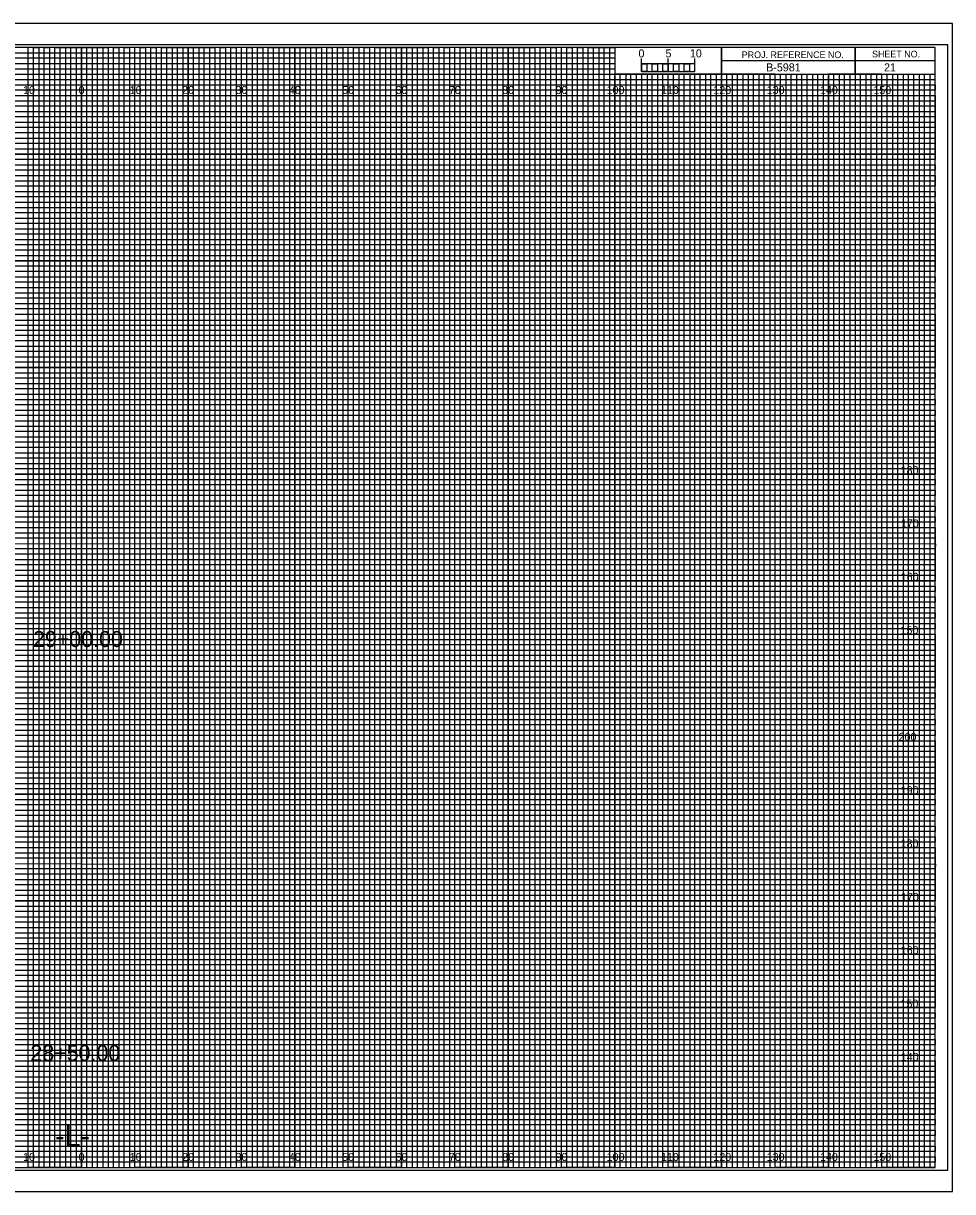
# Model space of a CAD drawing. Extents: x -13 to 323, y -5 to 4174.
# Drawn here: x 149.1 to 323.3, y 3295.5 to 3514.5 of the extents above; entities that cross this region are included whole.
import ezdxf

# ---------------------------------------------------------------- set-up
doc = ezdxf.new("R2010")
doc.units = 0
for name, color, linetype in [('Exist Cross Section Cell', 7, 'Continuous'), ('Exist XS Center Line Elevation Label', 7, 'Continuous'), ('Exist XS Ground Line', 7, 'Continuous'), ('Prop CMT Concrete Structures', 7, 'Continuous'), ('Prop CMT Guardrail Graphics', 7, 'Continuous'), ('Prop CMT Pvmt Course 1', 7, 'Continuous'), ('Prop CMT Pvmt Course 2', 7, 'Continuous'), ('Prop CMT Pvmt Course 3', 7, 'Continuous'), ('Prop CMT Pvmt Surface', 7, 'Continuous'), ('Prop CMT Shld Paved Course 1', 7, 'Continuous'), ('Prop CMT Shld Paved Course 2', 7, 'Continuous'), ('Prop CMT Shld Paved Course 3', 7, 'Continuous'), ('Prop CMT Subgrade Earthwork', 7, 'Continuous'), ('Prop XS Ditch Standard Text', 7, 'Continuous'), ('Prop XS SE Text', 7, 'Continuous'), ('Prop XS Side Slope Text', 7, 'Continuous'), ('Scratch_Level_0', 7, 'Continuous')]:
    doc.layers.add(name, color=color, linetype=linetype)

msp = doc.modelspace()

# ---------------------------------------------------------------- linework, layer by layer
at = {"layer": 'Exist XS Center Line Elevation Label'}
for points in [[(145, 3300), (155, 3300), (155, 3510), (165, 3510), (165, 3300), (175, 3300), (175, 3510), (185, 3510), (185, 3300), (195, 3300), (195, 3510), (205, 3510), (205, 3300), (215, 3300), (215, 3510), (225, 3510), (225, 3300), (235, 3300), (235, 3510), (245, 3510), (245, 3300), (255, 3300), (255, 3510), (259.93, 3510), (260, 3510), (260, 3505), (264.99, 3505), (264.99, 3300), (275, 3300), (275, 3505), (285, 3505), (285, 3300), (295, 3300), (295, 3505), (305, 3505), (305, 3300), (315, 3300), (315, 3505)], [(0, 3505), (275, 3505)], [(0, 3485), (320, 3485), (320, 3495), (0, 3495)], [(0, 3465), (320, 3465), (320, 3475), (0, 3475)], [(0, 3445), (320, 3445), (320, 3455), (0, 3455)], [(0, 3425), (320, 3425), (320, 3435), (0, 3435)], [(0, 3405), (320, 3405), (320, 3415), (0, 3415)], [(0, 3385), (320, 3385), (320, 3395), (0, 3395)], [(0, 3365), (320, 3365), (320, 3375), (0, 3375)], [(0, 3345), (320, 3345), (320, 3355), (0, 3355)], [(0, 3325), (320, 3325), (320, 3335), (0, 3335)], [(0, 3305), (320, 3305), (320, 3315), (0, 3315)]]:
    msp.add_lwpolyline(points, dxfattribs=at)
at = {"layer": 'Exist XS Ground Line'}
for p, q in [((150, 3510), (140, 3510)), ((150, 3300), (150, 3510)), ((170, 3510), (160, 3510)), ((160, 3510), (160, 3300)), ((170, 3300), (170, 3510)), ((190, 3510), (180, 3510)), ((180, 3510), (180, 3300)), ((190, 3300), (190, 3510)), ((210, 3510), (200, 3510)), ((200, 3510), (200, 3300)), ((210, 3300), (210, 3510)), ((230, 3510), (220, 3510)), ((220, 3510), (220, 3300)), ((230, 3300), (230, 3510)), ((250, 3510), (240, 3510)), ((240, 3510), (240, 3300)), ((250, 3300), (250, 3510)), ((260, 3510), (260, 3300)), ((270, 3300), (270, 3505)), ((290, 3505), (280, 3505)), ((280, 3505), (280, 3300)), ((290, 3300), (290, 3505)), ((310, 3505), (300, 3505)), ((300, 3505), (300, 3300)), ((310, 3300), (310, 3505)), ((160, 3300), (150, 3300)), ((180, 3300), (170, 3300)), ((200, 3300), (190, 3300)), ((220, 3300), (210, 3300)), ((240, 3300), (230, 3300)), ((260, 3300), (250, 3300)), ((280, 3300), (270, 3300)), ((300, 3300), (290, 3300)), ((320, 3300), (310, 3300)), ((320, 3300), (320, 3300))]:
    msp.add_line(p, q, dxfattribs=at)
for points in [[(0, 3500), (320, 3500), (320, 3490), (0, 3490)], [(0, 3480), (320, 3480), (320, 3470), (0, 3470)], [(0, 3460), (320, 3460), (320, 3450), (0, 3450)], [(0, 3440), (320, 3440), (320, 3430), (0, 3430)], [(0, 3420), (320, 3420), (320, 3410), (0, 3410)], [(0, 3400), (320, 3400), (320, 3390), (0, 3390)], [(0, 3380), (320, 3380), (320, 3370), (0, 3370)], [(0, 3360), (320, 3360), (320, 3350), (0, 3350)], [(0, 3340), (320, 3340), (320, 3330), (0, 3330)], [(0, 3320), (320, 3320), (320, 3310), (0, 3310)]]:
    msp.add_lwpolyline(points, dxfattribs=at)
at = {"layer": 'Prop CMT Pvmt Course 1'}
for p, q in [((323.3, 3514.5), (-13.4, 3514.5)), ((-13.4, 3295.5), (323.3, 3295.5))]:
    msp.add_line(p, q, dxfattribs=at)
at = {"layer": 'Prop CMT Pvmt Course 2'}
msp.add_lwpolyline([(-13.4, 3295.5), (323.3, 3295.5), (323.3, 3514.5), (-13.4, 3514.5)], close=True, dxfattribs=at)
at = {"layer": 'Prop CMT Pvmt Course 3'}
msp.add_lwpolyline([(-10.8, 3299.5), (322.4, 3299.5), (322.4, 3510.5), (-10.8, 3510.5)], close=True, dxfattribs=at)
at = {"layer": 'Prop CMT Shld Paved Course 1'}
for p, q in [((305, 3510), (305, 3505)), ((305, 3505), (305, 3510)), ((280, 3507.5), (280, 3505)), ((320, 3507.49), (280, 3507.49)), ((280, 3505), (320, 3505))]:
    msp.add_line(p, q, dxfattribs=at)
for points in [[(320, 3510), (0, 3510), (0, 3300), (320, 3300)], [(280, 3510), (260, 3510), (260, 3505.03), (280, 3505.03)], [(320, 3510), (280, 3510), (280, 3505), (320, 3505)]]:
    msp.add_lwpolyline(points, close=True, dxfattribs=at)
at = {"layer": 'Prop CMT Shld Paved Course 2'}
for p, q in [((267, 3505), (266.01, 3505)), ((266.01, 3505), (266.01, 3300)), ((267, 3300), (267, 3505)), ((269, 3505), (268, 3505)), ((268, 3505), (268, 3300)), ((269, 3300), (269, 3505)), ((266.01, 3300), (265, 3300)), ((268, 3300), (267, 3300))]:
    msp.add_line(p, q, dxfattribs=at)
for points in [[(150, 3300), (151, 3300), (151, 3510), (152, 3510), (152, 3300)], [(152, 3300), (153, 3300), (153, 3510), (154, 3510), (154, 3300)], [(155, 3300), (156, 3300), (156, 3510), (157, 3510), (157, 3300)], [(157, 3300), (158, 3300), (158, 3510), (159, 3510), (159, 3300)], [(160, 3300), (161, 3300), (161, 3510), (162, 3510), (162, 3300)], [(162, 3300), (163, 3300), (163, 3510), (164, 3510), (164, 3300)], [(165, 3300), (166, 3300), (166, 3510), (167, 3510), (167, 3300)], [(167, 3300), (168, 3300), (168, 3510), (169, 3510), (169, 3300)], [(170, 3300), (171, 3300), (171, 3510), (172, 3510), (172, 3300)], [(172, 3300), (173, 3300), (173, 3510), (174, 3510), (174, 3300)], [(175, 3300), (176, 3300), (176, 3510), (177, 3510), (177, 3300)], [(177, 3300), (178, 3300), (178, 3510), (179, 3510), (179, 3300)], [(180, 3300), (181, 3300), (181, 3510), (182, 3510), (182, 3300)], [(182, 3300), (183, 3300), (183, 3510), (184, 3510), (184, 3300)], [(185, 3300), (186, 3300), (186, 3510), (187, 3510), (187, 3300)], [(187, 3300), (188, 3300), (188, 3510), (189, 3510), (189, 3300)], [(190, 3300), (191, 3300), (191, 3510), (192, 3510), (192, 3300)], [(192, 3300), (193, 3300), (193, 3510), (194, 3510), (194, 3300)], [(195, 3300), (196, 3300), (196, 3510), (197, 3510), (197, 3300)], [(197, 3300), (198, 3300), (198, 3510), (199, 3510), (199, 3300)], [(200, 3300), (201, 3300), (201, 3510), (202, 3510), (202, 3300)], [(202, 3300), (203, 3300), (203, 3510), (204, 3510), (204, 3300)], [(205, 3300), (206, 3300), (206, 3510), (207, 3510), (207, 3300)], [(207, 3300), (208, 3300), (208, 3510), (209, 3510), (209, 3300)], [(210, 3300), (211, 3300), (211, 3510), (212, 3510), (212, 3300)], [(212, 3300), (213, 3300), (213, 3510), (214, 3510), (214, 3300)], [(215, 3300), (216, 3300), (216, 3510), (217, 3510), (217, 3300)], [(217, 3300), (218, 3300), (218, 3510), (219, 3510), (219, 3300)], [(220, 3300), (221, 3300), (221, 3510), (222, 3510), (222, 3300)], [(222, 3300), (223, 3300), (223, 3510), (224, 3510), (224, 3300)], [(225, 3300), (226, 3300), (226, 3510), (227, 3510), (227, 3300)], [(227, 3300), (228, 3300), (228, 3510), (229, 3510), (229, 3300)], [(230, 3300), (231, 3300), (231, 3510), (232, 3510), (232, 3300)], [(232, 3300), (233, 3300), (233, 3510), (234, 3510), (234, 3300)], [(235, 3300), (236, 3300), (236, 3510), (237, 3510), (237, 3300)], [(237, 3300), (238, 3300), (238, 3510), (239, 3510), (239, 3300)], [(240, 3300), (241, 3300), (241, 3510), (242, 3510), (242, 3300)], [(242, 3300), (243, 3300), (243, 3510), (244, 3510), (244, 3300)], [(245, 3300), (246, 3300), (246, 3510), (247, 3510), (247, 3300)], [(247, 3300), (248, 3300), (248, 3510), (249, 3510), (249, 3300)], [(250, 3300), (251, 3300), (251, 3510), (252, 3510), (252, 3300)], [(252, 3300), (253, 3300), (253, 3510), (254, 3510), (254, 3300)], [(255, 3300), (256, 3300), (256, 3510), (257, 3510), (257, 3300)], [(257, 3300), (258, 3300), (258, 3510), (259, 3510), (259, 3300)], [(260, 3300), (261, 3300), (261, 3505), (262.02, 3505), (262.02, 3300)], [(262, 3300), (263, 3300), (263, 3505), (263.99, 3505), (263.99, 3300)], [(270, 3300), (270.98, 3300), (270.98, 3505), (272, 3505), (272, 3300)], [(272, 3300), (273, 3300), (273, 3505), (274.05, 3505), (274.05, 3300)], [(275, 3300), (276, 3300), (276, 3505), (277, 3505), (277, 3300)], [(277, 3300), (278, 3300), (278, 3505), (279, 3505), (279, 3300)], [(280, 3300), (281, 3300), (281, 3505), (282, 3505), (282, 3300)], [(282, 3300), (283, 3300), (283, 3505), (284, 3505), (284, 3300)], [(285, 3300), (286, 3300), (286, 3505), (287, 3505), (287, 3300)], [(287, 3300), (288, 3300), (288, 3505), (289, 3505), (289, 3300)], [(290, 3300), (291, 3300), (291, 3505), (292, 3505), (292, 3300)], [(292, 3300), (293, 3300), (293, 3505), (294, 3505), (294, 3300)], [(295, 3300), (296, 3300), (296, 3505), (297, 3505), (297, 3300)], [(297, 3300), (298, 3300), (298, 3505), (299, 3505), (299, 3300)], [(300, 3300), (301, 3300), (301, 3505), (302, 3505), (302, 3300)], [(302, 3300), (303, 3300), (303, 3505), (304, 3505), (304, 3300)], [(305, 3300), (306, 3300), (306, 3505), (307, 3505), (307, 3300)], [(307, 3300), (308, 3300), (308, 3505), (309, 3505), (309, 3300)], [(310, 3300), (311, 3300), (311, 3505), (312, 3505), (312, 3300)], [(312, 3300), (313, 3300), (313, 3505), (314, 3505), (314, 3300)], [(315, 3300), (316, 3300), (316, 3505), (317, 3505), (317, 3300)], [(317, 3300), (318, 3300), (318, 3505), (319, 3505), (319, 3300)]]:
    msp.add_lwpolyline(points, dxfattribs=at)
at = {"layer": 'Prop CMT Shld Paved Course 3'}
for p, q in [((265, 3505.49), (265, 3507.9)), ((265, 3506.9), (265, 3507.9)), ((270, 3505.49), (270, 3507.9)), ((275, 3505.49), (275, 3507.9)), ((275, 3506.9), (275, 3507.9))]:
    msp.add_line(p, q, dxfattribs=at)
for points in [[(275, 3506.9), (265, 3506.9), (265, 3505.49), (275, 3505.49)], [(265, 3506.9), (266, 3506.9), (266, 3505.49), (265, 3505.49)], [(267, 3506.9), (268, 3506.9), (268, 3505.49), (267, 3505.49)], [(269, 3506.9), (270, 3506.9), (270, 3505.49), (269, 3505.49)], [(271, 3506.9), (272, 3506.9), (272, 3505.49), (271, 3505.49)], [(273, 3506.9), (274, 3506.9), (274, 3505.49), (273, 3505.49)]]:
    msp.add_lwpolyline(points, close=True, dxfattribs=at)
at = {"layer": 'Prop CMT Subgrade Earthwork'}
for p, q in [((150, 3300), (150, 3510)), ((160, 3300), (160, 3510)), ((170, 3300), (170, 3510)), ((180, 3300), (180, 3510)), ((190, 3300), (190, 3510)), ((200, 3300), (200, 3510)), ((210, 3300), (210, 3510)), ((220, 3300), (220, 3510)), ((230, 3300), (230, 3510)), ((240, 3300), (240, 3510)), ((250, 3300), (250, 3510)), ((260, 3300), (260, 3504.69)), ((270, 3300), (270, 3504.69)), ((280, 3300), (280, 3504.69)), ((290, 3300), (290, 3504.69)), ((300, 3300), (300, 3504.69)), ((310, 3300), (310, 3504.69)), ((0, 3500), (320, 3500)), ((0, 3490), (320, 3490)), ((0, 3480), (320, 3480)), ((0, 3470), (320, 3470)), ((0, 3460), (320, 3460)), ((0, 3450), (320, 3450)), ((0, 3440), (320, 3440)), ((0, 3430), (320, 3430)), ((0, 3420), (320, 3420)), ((0, 3410), (320, 3410)), ((0, 3400), (320, 3400)), ((0, 3390), (320, 3390)), ((0, 3380), (320, 3380)), ((0, 3370), (320, 3370)), ((0, 3360), (320, 3360)), ((0, 3350), (320, 3350)), ((0, 3340), (320, 3340)), ((0, 3330), (320, 3330)), ((0, 3320), (320, 3320)), ((0, 3310), (320, 3310))]:
    msp.add_line(p, q, dxfattribs=at)
at = {"layer": 'Scratch_Level_0'}
for p, q in [((0, 3509), (260, 3509)), ((260, 3509), (260, 3507.98)), ((260, 3507.98), (0, 3507.98)), ((0, 3507), (260, 3507)), ((260, 3507), (260, 3505.89)), ((260, 3505.89), (0, 3505.89)), ((0, 3504), (320, 3504))]:
    msp.add_line(p, q, dxfattribs=at)
for points in [[(0, 3503), (270, 3503), (320, 3503), (320, 3502), (0, 3502)], [(0, 3501), (320, 3501), (320, 3499), (0, 3499)], [(0, 3498), (320, 3498), (320, 3497), (0, 3496.98)], [(0, 3496), (320, 3496), (320, 3494), (0, 3494)], [(0, 3493), (320, 3493), (320, 3492), (0, 3492)], [(0, 3491), (320, 3491), (320, 3489), (0, 3489)], [(0, 3488), (320, 3488), (320, 3487), (0, 3487)], [(0, 3486), (320, 3486), (320, 3484), (0, 3484)], [(0, 3483), (320, 3483), (320, 3482), (0, 3482)], [(0, 3481), (320, 3481), (320, 3479), (0, 3479)], [(0, 3478), (320, 3478), (320, 3477), (0, 3477)], [(0, 3476), (320, 3476), (320, 3473.95), (320, 3473), (320, 3472), (0, 3472)], [(0, 3474), (320, 3474), (320, 3473), (0, 3473)], [(0, 3471), (320, 3471), (320, 3469), (0, 3469.03)], [(0, 3469.03), (320, 3469), (320, 3468), (0, 3468)], [(0, 3467), (320, 3467), (320, 3466), (0, 3466)], [(0, 3464), (320, 3464), (320, 3463), (0, 3463)], [(0, 3462), (320, 3462), (320, 3461), (0, 3461)], [(-0.07, 3458.89), (320, 3458.89), (320, 3457.88), (-0.07, 3457.88)], [(0, 3457), (320, 3457), (320, 3456), (0, 3456)], [(0, 3454), (320, 3454), (320, 3453), (0, 3453)], [(0, 3452), (320, 3452), (320, 3451), (0, 3451)], [(0, 3449), (320, 3449), (320, 3448), (0, 3448)], [(0, 3447), (320, 3447), (320, 3446), (0, 3446)], [(0, 3444), (320, 3444), (320, 3443), (0, 3443)], [(0, 3442), (320, 3442), (320, 3441), (0, 3441)], [(0, 3439), (320, 3439), (319.99, 3437.98), (0, 3438)], [(0, 3437), (320, 3437), (320, 3436), (0, 3436)], [(0, 3434), (320, 3434), (320, 3433), (0, 3433)], [(0, 3432), (320, 3432), (320, 3431), (0, 3431)], [(0, 3429), (320, 3429), (320, 3428), (0, 3428)], [(0, 3427), (320, 3427), (320, 3426), (0, 3426)], [(0, 3424), (320, 3424), (320, 3423), (0, 3423)], [(0, 3422), (320, 3422), (320, 3421), (0, 3421)], [(0, 3419), (320, 3419), (320, 3418), (0, 3418)], [(0, 3416.99), (320.07, 3416.91), (320, 3416), (0, 3416)], [(0, 3414), (320, 3414), (320, 3413), (0, 3413)], [(0, 3412), (320, 3412), (320, 3411), (0, 3411)], [(0, 3409), (320, 3409), (320, 3408), (0, 3408)], [(0, 3407), (320, 3407), (320, 3406), (0, 3406)], [(0, 3404), (320, 3404), (320, 3403), (0, 3403)], [(0, 3402), (320, 3402), (320, 3401), (0, 3401)], [(0, 3399), (320, 3399), (320, 3398), (0, 3398)], [(0, 3397), (320, 3397), (320, 3396), (0, 3396)], [(0, 3394), (320, 3394), (320, 3393), (0, 3393)], [(0, 3392), (320, 3392), (320, 3391), (0, 3391)], [(0, 3389), (320, 3389), (320, 3388), (0, 3388)], [(0, 3387), (320, 3387), (320, 3386), (0, 3386)], [(0, 3384), (320, 3384), (320, 3383), (0, 3383)], [(0, 3382), (320, 3382), (320, 3381), (0, 3381)], [(0, 3379), (320, 3379), (319.99, 3377.98), (0, 3378)], [(0, 3377), (320, 3377), (320, 3376), (0, 3376)], [(0, 3374), (320, 3374), (320, 3373), (0, 3373)], [(0, 3372), (320, 3372), (320, 3371), (0, 3371)], [(0, 3369), (320, 3369), (320, 3368), (0, 3368)], [(0, 3367), (320, 3367), (320, 3366), (0, 3366)], [(0, 3364), (320, 3364), (320, 3363), (0, 3363)], [(0, 3362), (320, 3362), (320, 3361), (0, 3361)], [(0, 3359), (320, 3359), (320, 3358), (0, 3358)], [(0, 3356.99), (320.07, 3356.91), (320, 3356), (0, 3356)], [(0, 3354), (320, 3354), (320, 3353), (0, 3353)], [(0, 3352), (320, 3352), (320, 3351), (0, 3351)], [(0, 3349), (320, 3349), (320, 3348), (0, 3348)], [(0, 3347), (320, 3347), (320, 3346), (0, 3346)], [(0, 3344), (320, 3344), (320, 3343), (0, 3343)], [(0, 3342), (320, 3342), (320, 3341), (0, 3341)], [(0, 3339), (320, 3339), (320, 3338), (0, 3338)], [(0, 3337), (320, 3337), (320, 3336), (0, 3336)], [(0, 3334), (320, 3334), (320, 3333), (0, 3333)], [(0, 3332), (320, 3332), (320, 3331), (0, 3331)], [(0, 3329), (320, 3329), (320, 3328), (0, 3328)], [(0, 3327), (320, 3327), (320, 3326), (0, 3326)], [(0, 3324), (320, 3324), (320, 3323), (0, 3323)], [(0, 3322), (320, 3322), (320, 3321), (0, 3321)], [(0, 3319), (320, 3319), (320, 3318), (0, 3318)], [(0, 3317), (320, 3317), (320, 3316), (0, 3316)], [(0, 3314), (320, 3314), (320, 3313), (0, 3313)], [(0, 3312), (320, 3312), (320, 3311), (0, 3311)], [(0, 3309), (320, 3309), (320, 3308), (0, 3308)], [(0, 3307), (320, 3307), (320, 3306), (0, 3306)], [(0, 3304), (320, 3304), (320, 3303), (0, 3303)], [(0, 3302), (320, 3302), (320, 3301), (0, 3301)]]:
    msp.add_lwpolyline(points, dxfattribs=at)

# ---------------------------------------------------------------- texts
at = {"layer": 'Exist Cross Section Cell'}
for s, p in [('10', (149.04, 3501.25)), ('0', (159.45, 3501.25)), ('0', (159.45, 3501.25)), ('10', (169.04, 3501.25)), ('20', (178.86, 3501.25)), ('30', (188.86, 3501.25)), ('40', (198.86, 3501.25)), ('50', (208.86, 3501.25)), ('60', (218.86, 3501.25)), ('70', (228.86, 3501.25)), ('80', (238.86, 3501.25)), ('90', (248.86, 3501.25)), ('100', (258.44, 3501.25)), ('110', (268.62, 3501.25)), ('120', (278.44, 3501.25)), ('130', (288.44, 3501.25)), ('140', (298.44, 3501.25)), ('150', (308.44, 3501.25)), ('10', (149.04, 3301.25)), ('0', (159.45, 3301.25)), ('0', (159.45, 3301.25)), ('10', (169.04, 3301.25)), ('20', (178.86, 3301.25)), ('30', (188.86, 3301.25)), ('40', (198.86, 3301.25)), ('50', (208.86, 3301.25)), ('60', (218.86, 3301.25)), ('70', (228.86, 3301.25)), ('80', (238.86, 3301.25)), ('90', (248.86, 3301.25)), ('100', (258.44, 3301.25)), ('110', (268.62, 3301.25)), ('120', (278.44, 3301.25)), ('130', (288.44, 3301.25)), ('140', (298.44, 3301.25)), ('150', (308.44, 3301.25))]:
    msp.add_text(s, height=1.5, dxfattribs=at).set_placement(p)
at = {"layer": 'Prop CMT Concrete Structures'}
for s, p in [('29+00.00', (150.9, 3397.59)), ('28+50.00', (150.41, 3319.99))]:
    msp.add_text(s, height=3, dxfattribs=at).set_placement(p)
at = {"layer": 'Prop CMT Guardrail Graphics'}
for s, p in [('180', (313.55, 3430)), ('170', (313.61, 3420)), ('160', (313.57, 3410)), ('150', (313.52, 3400)), ('200', (313.17, 3380)), ('190', (313.57, 3370)), ('180', (313.55, 3360)), ('170', (313.61, 3350)), ('160', (313.57, 3340)), ('150', (313.52, 3330)), ('140', (313.57, 3320))]:
    msp.add_text(s, height=1.5, dxfattribs=at).set_placement(p)
at = {"layer": 'Prop CMT Pvmt Surface'}
for s, p in [('5', (269.47, 3508.12)), ('10', (274.04, 3508.12))]:
    msp.add_text(s, height=1.5, dxfattribs=at).set_placement(p)
at = {"layer": 'Prop CMT Shld Paved Course 1'}
for s, p in [('PROJ. REFERENCE NO.', (283.77, 3507.99)), ('SHEET NO.', (308.19, 3508.12))]:
    msp.add_text(s, height=1.25, dxfattribs=at).set_placement(p)
at = {"layer": 'Prop CMT Shld Paved Course 3'}
msp.add_text('0', height=1.5, dxfattribs=at).set_placement((264.41, 3508.12))
at = {"layer": 'Prop XS Ditch Standard Text'}
msp.add_text('-L-', height=4, dxfattribs=at).set_placement((155.06, 3304))
at = {"layer": 'Prop XS SE Text'}
msp.add_text(' B-5981', height=1.5, dxfattribs=at).set_placement((287.79, 3505.5))
at = {"layer": 'Prop XS Side Slope Text'}
msp.add_text('21', height=1.5, dxfattribs=at).set_placement((310.44, 3505.5))

doc.saveas('drawing.dxf')
